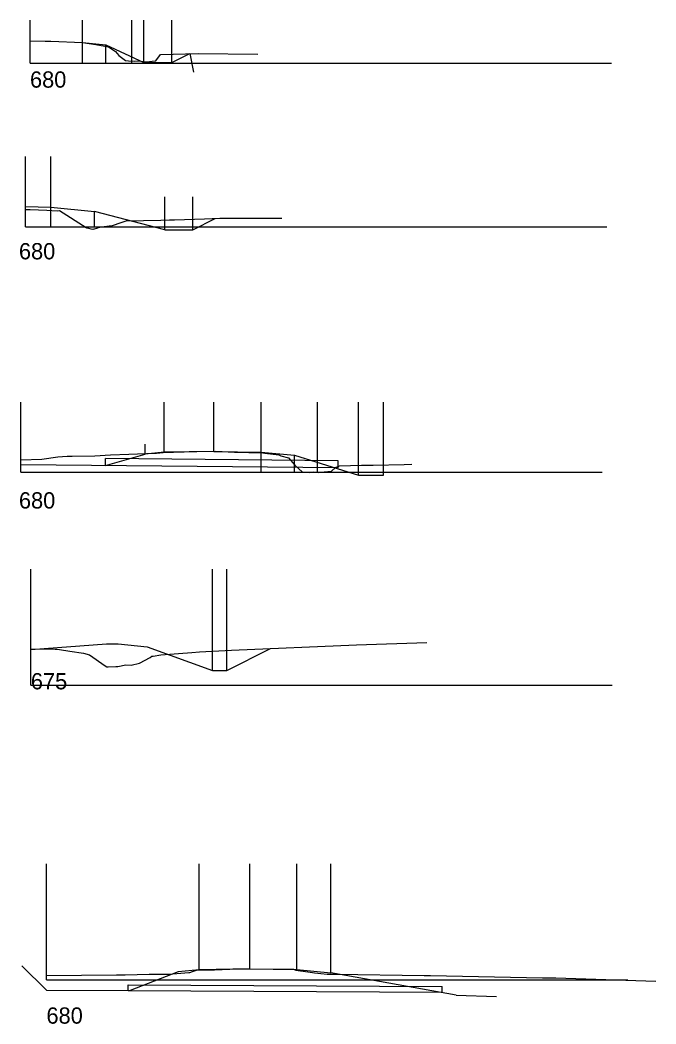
# Model space of a CAD drawing. Extents: x 157201 to 163282, y 424960 to 427200.
# Drawn here: x 161023.5 to 161132.8, y 424960.2 to 425133 of the extents above; entities that cross this region are included whole.
import ezdxf

# ---------------------------------------------------------------- set-up
doc = ezdxf.new("R2010")
doc.units = 0
for name, color, linetype in [('GE_P_Alignment_100_Bearings', 7, 'Continuous'), ('PM_X_Stop_Line', 7, 'Continuous'), ('PV_X_Shoulder', 7, 'Continuous'), ('RD_X_Gate', 7, 'Continuous'), ('UT_X_Sanitary_Cells', 7, 'Continuous'), ('UT_X_Water_Cells', 7, 'Continuous')]:
    doc.layers.add(name, color=color, linetype=linetype)

msp = doc.modelspace()

# ---------------------------------------------------------------- linework, layer by layer
at = {"layer": 'GE_P_Alignment_100_Bearings'}
for p, q in [((161025.17, 425125.56), (161025.17, 425132.96)), ((161034.22, 425125.56), (161034.22, 425132.96)), ((161042.67, 425125.56), (161042.67, 425132.96)), ((161044.77, 425125.63), (161044.77, 425132.96)), ((161049.55, 425125.63), (161049.55, 425132.96)), ((161034.22, 425129.08), (161038.24, 425128.68)), ((161038.24, 425125.56), (161038.24, 425128.68)), ((161038.24, 425128.68), (161044.77, 425125.63)), ((161044.77, 425125.63), (161049.55, 425125.63)), ((161049.55, 425125.63), (161052.65, 425127.18)), ((161052.65, 425127.18), (161053.31, 425123.99)), ((161025.17, 425125.56), (161125.17, 425125.56)), ((161024.39, 425097.39), (161024.39, 425109.46)), ((161028.77, 425097.39), (161028.77, 425109.46)), ((161024.39, 425100.91), (161028.77, 425100.79)), ((161028.77, 425100.79), (161036.27, 425100.04)), ((161036.27, 425097.39), (161036.27, 425100.04)), ((161048.34, 425096.89), (161036.27, 425100.04)), ((161053.18, 425096.89), (161057.04, 425098.82)), ((161024.39, 425097.39), (161124.39, 425097.39)), ((161048.34, 425096.89), (161053.18, 425096.89)), ((161023.6, 425055.15), (161023.6, 425067.22)), ((161028, 424966.05), (161023.78, 424970.26))]:
    msp.add_line(p, q, dxfattribs=at)
at = {"layer": 'PM_X_Stop_Line'}
msp.add_line((161074.63, 425055.15), (161074.63, 425067.22), dxfattribs=at)
at = {"layer": 'PV_X_Shoulder'}
for p, q in [((161048.34, 425096.89), (161048.34, 425102.57)), ((161053.18, 425096.89), (161053.18, 425102.57))]:
    msp.add_line(p, q, dxfattribs=at)
at = {"layer": 'RD_X_Gate'}
for p, q in [((161044.98, 425058.3), (161044.98, 425059.97)), ((161048.27, 425058.6), (161044.98, 425058.3)), ((161025.32, 425018.51), (161025.32, 425038.47)), ((161056.56, 425021.06), (161056.56, 425038.47)), ((161059, 425021.06), (161059, 425038.47)), ((161025.32, 425024.64), (161038.32, 425025.64)), ((161038.32, 425025.64), (161040.32, 425025.62)), ((161040.32, 425025.62), (161045.32, 425025.12)), ((161045.32, 425025.12), (161056.56, 425021.06)), ((161059, 425021.06), (161066.51, 425024.82)), ((161056.56, 425021.06), (161059, 425021.06)), ((161025.32, 425018.51), (161125.32, 425018.51))]:
    msp.add_line(p, q, dxfattribs=at)
at = {"layer": 'UT_X_Sanitary_Cells'}
for p, q in [((161048.27, 425058.6), (161048.27, 425067.22)), ((161056.77, 425058.75), (161056.77, 425067.22)), ((161064.94, 425055.15), (161064.94, 425067.22)), ((161081.67, 425054.65), (161081.67, 425067.22)), ((161085.97, 425054.65), (161085.97, 425067.22)), ((161038.17, 425056.3), (161044.98, 425058.3)), ((161056.77, 425058.75), (161048.27, 425058.6)), ((161056.77, 425058.75), (161064.94, 425058.64)), ((161064.94, 425058.64), (161070.66, 425058.08)), ((161078.17, 425057.15), (161038.17, 425057.55)), ((161038.17, 425056.3), (161038.17, 425057.55)), ((161070.66, 425055.15), (161070.66, 425058.08)), ((161070.66, 425058.08), (161081.67, 425054.65)), ((161078.17, 425055.9), (161078.17, 425057.15)), ((161078.17, 425055.9), (161023.6, 425056.44)), ((161023.6, 425055.15), (161123.6, 425055.15)), ((161081.67, 425054.65), (161085.97, 425054.65)), ((161028, 424967.84), (161028, 424987.8)), ((161054.25, 424969.55), (161054.25, 424987.8)), ((161062.99, 424969.73), (161062.99, 424987.8)), ((161071.08, 424969.63), (161071.08, 424987.8)), ((161076.9, 424969.05), (161076.9, 424987.8)), ((161050.63, 424969.19), (161042.41, 424965.98)), ((161054.25, 424969.55), (161050.63, 424969.19)), ((161062.99, 424969.73), (161054.25, 424969.55)), ((161062.99, 424969.73), (161071.08, 424969.63)), ((161071.08, 424969.63), (161076.9, 424969.05)), ((161098.45, 424965.19), (161076.9, 424969.05)), ((161028, 424967.84), (161128, 424967.84)), ((161042.06, 424966.98), (161096.06, 424966.71)), ((161042.06, 424965.98), (161042.06, 424966.98)), ((161028, 424966.05), (161042.41, 424965.98)), ((161042.06, 424965.98), (161096.06, 424965.71)), ((161096.06, 424965.71), (161096.06, 424966.71)), ((161098.45, 424965.19), (161105.43, 424964.97))]:
    msp.add_line(p, q, dxfattribs=at)
at = {"layer": 'UT_X_Water_Cells'}
for points in [[(161025.17, 425129.37), (161027.76, 425129.35), (161028.74, 425129.33), (161034.22, 425129.08), (161036.52, 425128.77), (161038.68, 425128.38), (161039.85, 425127.55), (161040.45, 425126.88), (161041.58, 425125.98), (161042.11, 425125.94), (161043.16, 425125.9), (161043.73, 425125.94), (161045.29, 425125.77), (161046.19, 425125.9), (161046.8, 425125.92), (161047.63, 425127.03), (161047.64, 425127.04), (161054.09, 425127.22), (161064.37, 425127.07)], [(161024.39, 425100.38), (161025.17, 425100.38), (161028.09, 425100.26), (161029.82, 425100.15), (161030.22, 425100.18), (161034.82, 425097.29), (161034.83, 425097.27), (161034.89, 425097.24), (161034.9, 425097.24), (161035.01, 425097.21), (161035.84, 425097), (161036, 425097.03), (161036.07, 425097.01), (161036.86, 425097.24), (161036.87, 425097.24), (161036.91, 425097.25), (161037.54, 425097.37), (161038.77, 425097.55), (161039.2, 425097.58), (161039.2, 425097.58), (161041.02, 425098.19), (161041.04, 425098.19), (161041.69, 425098.4), (161047.68, 425098.52), (161049.19, 425098.59), (161050.01, 425098.6), (161055.21, 425098.74), (161057.83, 425098.86), (161068.48, 425098.89)], [(161023.6, 425057.28), (161027.23, 425057.41), (161029.98, 425057.82), (161031.54, 425057.91), (161032.41, 425057.92), (161036.33, 425057.97), (161039.02, 425058.17), (161042.18, 425058.26), (161046.7, 425058.43), (161046.9, 425058.44), (161048.1, 425058.56), (161051.71, 425058.67), (161053.87, 425058.73), (161057.12, 425058.76), (161060.33, 425058.64), (161065.19, 425058.49), (161065.57, 425058.47), (161067.96, 425058.15), (161068.3, 425058.01), (161069.64, 425057.65), (161070.71, 425056.39), (161072.04, 425055.17), (161072.51, 425055.16), (161073.24, 425055.14), (161073.95, 425055.21), (161074.8, 425055.12), (161075.37, 425055.2), (161075.75, 425055.23), (161077, 425055.35), (161077.72, 425055.99), (161078.41, 425056.29), (161082.17, 425056.39), (161084.21, 425056.39), (161089.55, 425056.48), (161090.86, 425056.53)], [(161025.32, 425024.76), (161029.51, 425024.72), (161029.76, 425024.7), (161030.27, 425024.67), (161032.01, 425024.4), (161034.38, 425024.02), (161035.41, 425023.77), (161038.1, 425021.83), (161038.38, 425021.69), (161038.41, 425021.69), (161038.64, 425021.69), (161039.91, 425021.73), (161040.3, 425021.72), (161041.63, 425022.02), (161042.55, 425021.97), (161043.98, 425022.33), (161045.85, 425023.27), (161046.12, 425023.51), (161046.34, 425023.54), (161047.67, 425023.72), (161053.01, 425024.17), (161054.3, 425024.28), (161059.81, 425024.53), (161081.33, 425025.46), (161093.42, 425025.87)], [(161028, 424968.57), (161040.06, 424968.69), (161041.54, 424968.71), (161045.67, 424968.78), (161048.84, 424968.82), (161049.03, 424968.83), (161052.48, 424969.07), (161052.57, 424969.08), (161052.68, 424969.1), (161052.81, 424969.13), (161052.97, 424969.18), (161053.83, 424969.47), (161056.91, 424969.58), (161059.53, 424969.67), (161062.89, 424969.71), (161066.97, 424969.66), (161070.48, 424969.64), (161070.91, 424969.48), (161072.96, 424969.22), (161073.77, 424969.09), (161074.12, 424969.04), (161076.28, 424968.8), (161077.8, 424968.82), (161092.94, 424968.59), (161093.04, 424968.59), (161093.18, 424968.59), (161094.07, 424968.58), (161113.34, 424968.19), (161115.59, 424968.15), (161132.83, 424967.63)]]:
    msp.add_lwpolyline(points, dxfattribs=at)

# ---------------------------------------------------------------- texts
at = {"layer": 'GE_P_Alignment_100_Bearings'}
for p in [(161025.17, 425121.33), (161023.27, 425091.79), (161023.27, 425048.92)]:
    msp.add_text('680', height=2.8, dxfattribs=at).set_placement(p)
at = {"layer": 'RD_X_Gate'}
msp.add_text('675', height=2.8, dxfattribs=at).set_placement((161025.32, 425017.81))
at = {"layer": 'UT_X_Sanitary_Cells'}
msp.add_text('680', height=2.8, dxfattribs=at).set_placement((161028, 424960.29))

doc.saveas('drawing.dxf')
